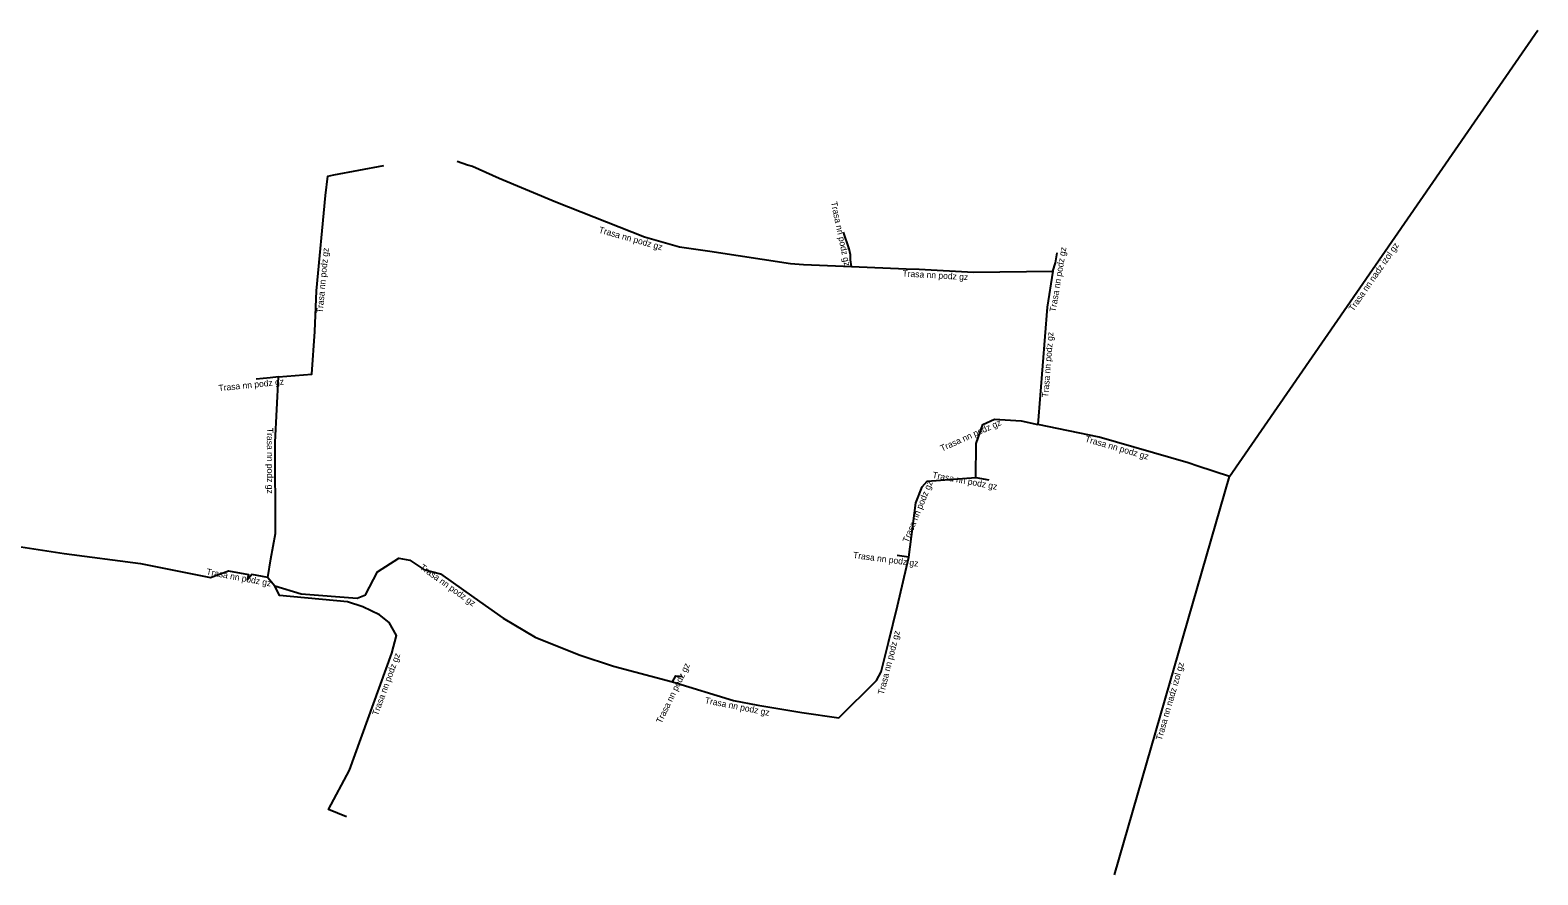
# Model space of a CAD drawing. Extents: x -771127 to -770600, y -1049993 to -1049871.
# Drawn here: x -770718.3 to -770599.9, y -1049989.6 to -1049923.2 of the extents above; entities that cross this region are included whole.
import ezdxf

# ---------------------------------------------------------------- set-up
doc = ezdxf.new("R2010")
doc.units = 0
doc.layers.add('Popiskový text - Ostatní atributy Trasy', color=7, linetype='Continuous')
doc.layers.add('Spojnice NN', color=7, linetype='Continuous')

msp = doc.modelspace()

# ---------------------------------------------------------------- linework, layer by layer
at = {"layer": 'Spojnice NN'}
for points in [[(-770624.1, -1049958.27), (-770599.89, -1049923.2)], [(-770698.79, -1049950.43), (-770696.18, -1049950.22), (-770695.93, -1049946.87), (-770695.81, -1049943.69), (-770695.11, -1049936.2), (-770694.91, -1049934.66), (-770694.44, -1049934.57), (-770690.53, -1049933.82)], [(-770684.76, -1049933.48), (-770683.94, -1049933.77), (-770683.57, -1049933.88), (-770681.47, -1049934.83), (-770677.02, -1049936.69), (-770670.06, -1049939.44), (-770667.29, -1049940.22), (-770664.91, -1049940.55), (-770658.58, -1049941.54), (-770657.56, -1049941.61), (-770653.78, -1049941.77)], [(-770653.78, -1049941.77), (-770653.86, -1049941.23), (-770653.88, -1049940.84), (-770653.98, -1049940.37), (-770654.41, -1049939.06)], [(-770637.97, -1049942.13), (-770637.77, -1049941.47), (-770637.64, -1049940.7)], [(-770653.78, -1049941.77), (-770649.51, -1049941.95), (-770648.47, -1049941.97), (-770644.22, -1049942.21), (-770637.97, -1049942.13)], [(-770637.97, -1049942.13), (-770638.42, -1049944.95), (-770639.16, -1049954.17)], [(-770698.79, -1049950.43), (-770699.45, -1049950.5), (-770700.56, -1049950.61)], [(-770699.64, -1049966.2), (-770699.39, -1049964.74), (-770699.04, -1049962.74), (-770699.06, -1049955.56), (-770698.79, -1049950.43)], [(-770644.03, -1049958.35), (-770643.99, -1049955.68), (-770643.48, -1049954.17), (-770642.57, -1049953.76), (-770640.47, -1049953.88), (-770639.16, -1049954.17)], [(-770624.1, -1049958.27), (-770626.59, -1049957.44), (-770627.35, -1049957.19), (-770634.34, -1049955.18), (-770639.16, -1049954.17)], [(-770649.28, -1049964.59), (-770648.74, -1049960.32), (-770648.23, -1049959.07), (-770647.84, -1049958.64), (-770644.03, -1049958.35)], [(-770644.03, -1049958.35), (-770643.02, -1049958.53)], [(-770633.15, -1049989.55), (-770624.1, -1049958.27)], [(-770743.09, -1049959.2), (-770740.88, -1049959.71), (-770739.04, -1049960.49), (-770736.59, -1049961.05), (-770731.72, -1049961.78), (-770729.71, -1049962.19), (-770722.45, -1049963.27), (-770715.62, -1049964.3), (-770709.62, -1049965.1), (-770704.14, -1049966.19), (-770702.73, -1049965.66), (-770701.16, -1049965.95), (-770701.25, -1049966.41)], [(-770699.64, -1049966.2), (-770699.09, -1049966.85), (-770697.02, -1049967.47), (-770692.61, -1049967.83), (-770691.97, -1049967.55), (-770691.03, -1049965.75), (-770689.35, -1049964.69), (-770688.47, -1049964.84), (-770687.39, -1049965.57), (-770686.06, -1049965.9), (-770683.44, -1049967.76), (-770681.14, -1049969.4), (-770678.63, -1049970.89), (-770675.17, -1049972.26), (-770672.48, -1049973.17), (-770667.84, -1049974.4)], [(-770654.78, -1049977.22), (-770651.82, -1049974.28), (-770651.46, -1049973.6), (-770650.88, -1049971.3), (-770650.17, -1049968.43), (-770649.28, -1049964.59)], [(-770649.28, -1049964.59), (-770650.21, -1049964.47)], [(-770699.64, -1049966.2), (-770700.89, -1049965.97), (-770701.25, -1049966.41)], [(-770693.46, -1049984.99), (-770694.86, -1049984.42), (-770693.23, -1049981.33), (-770689.88, -1049972.15), (-770689.52, -1049970.75), (-770690.09, -1049969.73), (-770690.86, -1049969.12), (-770692.17, -1049968.5), (-770693.38, -1049968.11), (-770698.72, -1049967.6), (-770699.09, -1049966.85)], [(-770667.84, -1049974.4), (-770667.6, -1049973.92), (-770667.08, -1049973.98)], [(-770667.84, -1049974.4), (-770663.06, -1049975.85), (-770661.15, -1049976.23), (-770657.7, -1049976.79), (-770654.78, -1049977.22)]]:
    msp.add_lwpolyline(points, dxfattribs=at)

# ---------------------------------------------------------------- texts
at = {"layer": 'Popiskový text - Ostatní atributy Trasy'}
for s, rotation, p in [('Trasa nn podz gz', 282.0115, (-770655.42, -1049936.72)), ('Trasa nn podz gz', 344.2734, (-770673.68, -1049939.1)), ('Trasa nn nadz izol gz', 55.3751, (-770614.38, -1049945.33)), ('Trasa nn podz gz', 84.6608, (-770695.32, -1049945.45)), ('Trasa nn podz gz', 80.5377, (-770637.76, -1049945.37)), ('Trasa nn podz gz', 356.7679, (-770649.8, -1049942.55)), ('Trasa nn podz gz', 85.4208, (-770638.34, -1049952.07)), ('Trasa nn podz gz', 5.9149, (-770703.48, -1049951.57)), ('Trasa nn podz gz', 24.1257, (-770646.69, -1049956.31)), ('Trasa nn podz gz', 270.1596, (-770699.71, -1049954.45)), ('Trasa nn podz gz', 343.9762, (-770635.49, -1049955.52)), ('Trasa nn podz gz', 67.838, (-770649.34, -1049963.5)), ('Trasa nn podz gz', 349.551, (-770647.47, -1049958.37)), ('Trasa nn podz gz', 352.5057, (-770653.69, -1049964.67)), ('Trasa nn podz gz', 349.5742, (-770704.49, -1049965.97)), ('Trasa nn podz gz', 324.5536, (-770687.74, -1049965.5)), ('Trasa nn podz gz', 75.6485, (-770651.26, -1049975.44)), ('Trasa nn podz gz', 69.9518, (-770690.99, -1049977.09)), ('Trasa nn podz gz', 64.0989, (-770668.72, -1049977.71)), ('Trasa nn nadz izol gz', 73.8796, (-770629.43, -1049979.03)), ('Trasa nn podz gz', 348.8803, (-770665.34, -1049976.07))]:
    msp.add_text(s, height=0.5, rotation=rotation, dxfattribs=at).set_placement(p)

doc.saveas('drawing.dxf')
